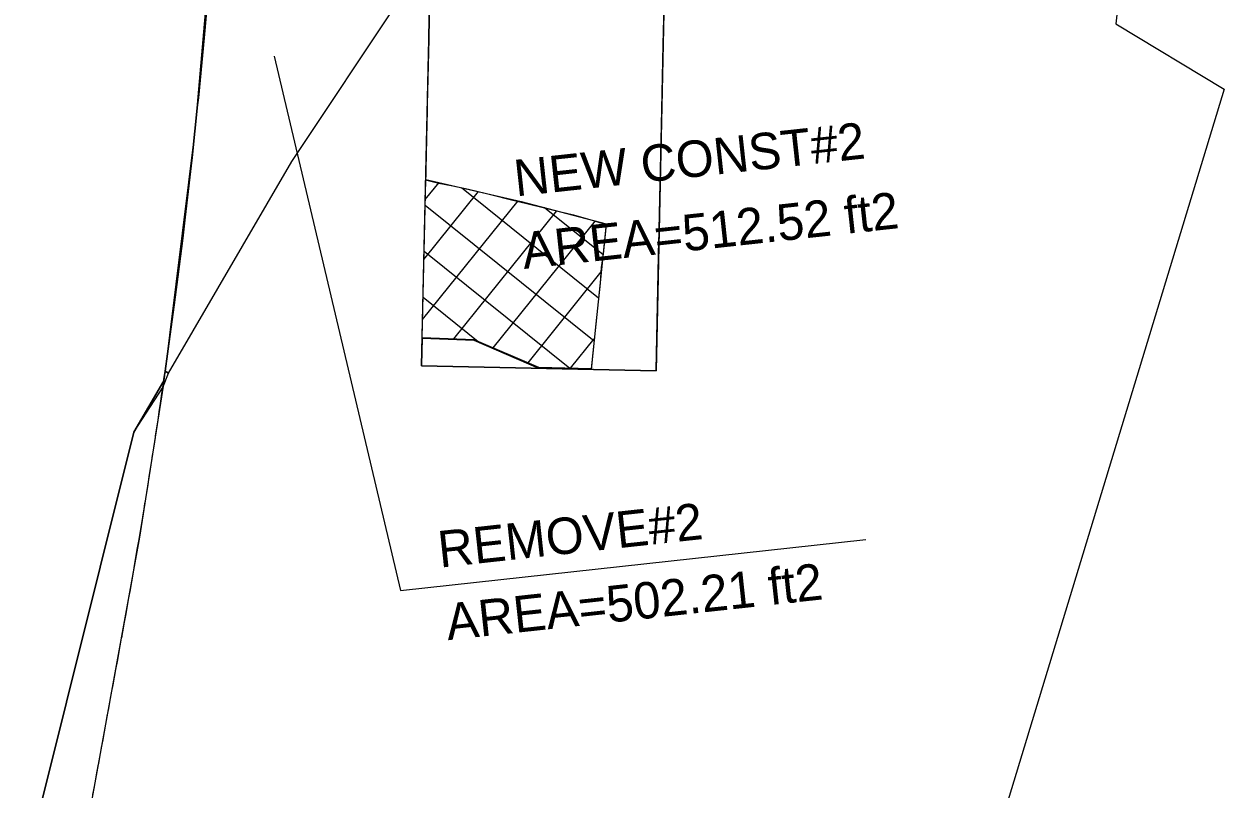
# Model space of a CAD drawing. Extents: x 1509538 to 1510847, y 401283 to 402022.
# Drawn here: x 1509791.8 to 1509883.9, y 401509.5 to 401568.2 of the extents above; entities that cross this region are included whole.
import ezdxf

# ---------------------------------------------------------------- set-up
doc = ezdxf.new("R2010")
doc.units = 0
for name, color, linetype in [('LAWE_P_T', 7, 'Continuous'), ('Level 10', 7, 'Continuous'), ('Level 2', 7, 'Continuous'), ('Level 24', 7, 'Continuous'), ('Level 3', 7, 'Continuous'), ('Level 4', 7, 'Continuous'), ('Level 7', 7, 'Continuous')]:
    doc.layers.add(name, color=color, linetype=linetype)

msp = doc.modelspace()

# ---------------------------------------------------------------- linework, layer by layer
at = {"layer": 'LAWE_P_T'}
msp.add_lwpolyline([(1509810.979, 401565.723), (1509820.68, 401524.728), (1509856.38, 401528.62)], dxfattribs=at)
at = {"layer": 'Level 10'}
for p, q in [((1509805.109, 401561.991), (1509805.163, 401562.527)), ((1509803.591, 401548.774), (1509803.964, 401551.755)), ((1509803.315, 401546.646), (1509803.591, 401548.774)), ((1509802.436, 401540.299), (1509802.86, 401541.4)), ((1509802.86, 401541.4), (1509802.614, 401541.544)), ((1509802.102, 401539.785), (1509802.436, 401540.299))]:
    msp.add_line(p, q, dxfattribs=at)
for points in [[(1509805.163, 401562.527), (1509805.605, 401567.117), (1509806.006, 401571.716), (1509806.049, 401572.248), (1509806.13, 401573.256), (1509806.21, 401574.264)], [(1509803.964, 401551.755), (1509804.156, 401553.354), (1509804.562, 401556.87), (1509804.68, 401557.938), (1509805.109, 401561.991)], [(1509802.614, 401541.544), (1509802.985, 401544.2), (1509803.315, 401546.646)], [(1509792.458, 401505.796), (1509800.217, 401536.878), (1509802.102, 401539.785)]]:
    msp.add_lwpolyline(points, dxfattribs=at)
at = {"layer": 'Level 2'}
for p, q in [((1509805.109, 401561.991), (1509805.163, 401562.527)), ((1509822.569, 401554.71), (1509823.627, 401556.027)), ((1509825.355, 401555.629), (1509835.868, 401547.182)), ((1509822.363, 401545.513), (1509829.687, 401554.629)), ((1509822.466, 401550.111), (1509826.657, 401555.328)), ((1509822.559, 401554.283), (1509835.521, 401543.87)), ((1509824.755, 401544.019), (1509832.657, 401553.855)), ((1509831.729, 401554.1), (1509836.216, 401550.495)), ((1509827.792, 401543.328), (1509835.621, 401553.074)), ((1509803.591, 401548.774), (1509803.964, 401551.755)), ((1509822.48, 401550.755), (1509833.67, 401541.765)), ((1509830.457, 401542.175), (1509836.077, 401549.17)), ((1509803.315, 401546.646), (1509803.591, 401548.774)), ((1509822.402, 401547.226), (1509826.626, 401543.832)), ((1509833.718, 401541.764), (1509835.537, 401544.028)), ((1509802.436, 401540.299), (1509802.86, 401541.4)), ((1509802.86, 401541.4), (1509802.614, 401541.544)), ((1509802.102, 401539.785), (1509802.436, 401540.299))]:
    msp.add_line(p, q, dxfattribs=at)
for points in [[(1509805.163, 401562.527), (1509805.605, 401567.117), (1509806.006, 401571.716), (1509806.049, 401572.248), (1509806.13, 401573.256), (1509806.21, 401574.264)], [(1509802.507, 401540.796), (1509802.525, 401540.921), (1509802.614, 401541.544), (1509802.985, 401544.2), (1509803.315, 401546.646), (1509803.591, 401548.774), (1509803.964, 401551.755), (1509804.156, 401553.354), (1509804.562, 401556.87), (1509804.68, 401557.938), (1509805.109, 401561.991), (1509805.163, 401562.527), (1509805.605, 401567.117), (1509805.605, 401567.119), (1509806.006, 401571.716)], [(1509803.964, 401551.755), (1509804.156, 401553.354), (1509804.562, 401556.87), (1509804.68, 401557.938), (1509805.109, 401561.991)], [(1509802.614, 401541.544), (1509802.985, 401544.2), (1509803.315, 401546.646)], [(1509772.308, 401394.175), (1509775.656, 401414.305), (1509783.793, 401462.538), (1509792.458, 401505.796), (1509800.217, 401536.878), (1509802.507, 401540.796)], [(1509792.458, 401505.796), (1509800.217, 401536.878), (1509802.102, 401539.785)]]:
    msp.add_lwpolyline(points, dxfattribs=at)
msp.add_lwpolyline([(1509822.603, 401556.263), (1509829.941, 401554.57), (1509836.463, 401552.852), (1509835.965, 401548.102), (1509835.296, 401541.728), (1509831.283, 401541.818), (1509826.334, 401543.959), (1509822.332, 401544.113)], close=True, dxfattribs=at)
at = {"layer": 'Level 24'}
msp.add_lwpolyline([(1509829.75, 401765.911), (1509866.097, 401667.732), (1509876.615, 401577.466), (1509875.566, 401568.188), (1509883.853, 401563.183), (1509866.769, 401506.877), (1509856.531, 401476.729), (1509809.074, 401412), (1509809.101, 401403.538), (1509796.557, 401386.395), (1509783.485, 401379.525), (1509778.168, 401371.598), (1509774.096, 401368.359), (1509767.585, 401349.346), (1509764.231, 401344.649), (1509737.941, 401349.46)], dxfattribs=at)
at = {"layer": 'Level 3'}
for p, q in [((1509822.948, 401571.989), (1509822.838, 401567.017)), ((1509822.28, 401541.962), (1509840.275, 401541.562))]:
    msp.add_line(p, q, dxfattribs=at)
for points in [[(1509840.275, 401541.562), (1509840.277, 401541.623), (1509840.388, 401546.621), (1509840.499, 401551.62), (1509840.502, 401551.752), (1509840.505, 401551.883), (1509840.508, 401552.015), (1509840.511, 401552.146), (1509840.514, 401552.278), (1509840.517, 401552.409), (1509840.52, 401552.541), (1509840.523, 401552.672), (1509840.526, 401552.804), (1509840.529, 401552.936), (1509840.532, 401553.067), (1509840.534, 401553.199), (1509840.537, 401553.33), (1509840.54, 401553.462), (1509840.543, 401553.593), (1509840.546, 401553.725), (1509840.549, 401553.856), (1509840.552, 401553.988), (1509840.555, 401554.119), (1509840.558, 401554.251), (1509840.561, 401554.383), (1509840.564, 401554.514), (1509840.567, 401554.646), (1509840.57, 401554.777), (1509840.573, 401554.909), (1509840.575, 401555.04), (1509840.578, 401555.172), (1509840.581, 401555.303), (1509840.584, 401555.435), (1509840.587, 401555.566), (1509840.59, 401555.698), (1509840.593, 401555.83), (1509840.596, 401555.961), (1509840.599, 401556.093), (1509840.602, 401556.224), (1509840.605, 401556.356), (1509840.608, 401556.487), (1509840.611, 401556.619), (1509840.614, 401556.75), (1509840.616, 401556.882), (1509840.619, 401557.013), (1509840.622, 401557.145), (1509840.625, 401557.277), (1509840.628, 401557.408), (1509840.631, 401557.54), (1509840.634, 401557.671), (1509840.637, 401557.803), (1509840.64, 401557.934), (1509840.643, 401558.066), (1509840.646, 401558.197), (1509840.649, 401558.329), (1509840.652, 401558.46), (1509840.655, 401558.592), (1509840.657, 401558.724), (1509840.66, 401558.855), (1509840.663, 401558.987), (1509840.666, 401559.118), (1509840.669, 401559.25), (1509840.672, 401559.381), (1509840.675, 401559.513), (1509840.678, 401559.644), (1509840.681, 401559.776), (1509840.684, 401559.908), (1509840.687, 401560.039), (1509840.69, 401560.171), (1509840.693, 401560.302), (1509840.696, 401560.434), (1509840.698, 401560.565), (1509840.701, 401560.697), (1509840.704, 401560.828), (1509840.707, 401560.96), (1509840.71, 401561.091), (1509840.713, 401561.223), (1509840.716, 401561.355), (1509840.719, 401561.486), (1509840.722, 401561.618), (1509840.833, 401566.616), (1509840.944, 401571.615)], [(1509822.838, 401567.017), (1509822.726, 401562.018), (1509822.723, 401561.887), (1509822.72, 401561.755), (1509822.718, 401561.624), (1509822.715, 401561.492), (1509822.712, 401561.36), (1509822.709, 401561.229), (1509822.706, 401561.097), (1509822.703, 401560.966), (1509822.7, 401560.834), (1509822.697, 401560.703), (1509822.694, 401560.571), (1509822.691, 401560.44), (1509822.688, 401560.308), (1509822.685, 401560.177), (1509822.682, 401560.045), (1509822.679, 401559.913), (1509822.677, 401559.782), (1509822.674, 401559.65), (1509822.671, 401559.519), (1509822.668, 401559.387), (1509822.665, 401559.256), (1509822.662, 401559.124), (1509822.659, 401558.993), (1509822.656, 401558.861), (1509822.653, 401558.73), (1509822.65, 401558.598), (1509822.647, 401558.466), (1509822.644, 401558.335), (1509822.641, 401558.203), (1509822.638, 401558.072), (1509822.636, 401557.94), (1509822.633, 401557.809), (1509822.63, 401557.677), (1509822.627, 401557.546), (1509822.624, 401557.414), (1509822.621, 401557.283), (1509822.618, 401557.151), (1509822.615, 401557.019), (1509822.612, 401556.888), (1509822.609, 401556.756), (1509822.606, 401556.625), (1509822.603, 401556.493), (1509822.6, 401556.362), (1509822.597, 401556.23), (1509823.624, 401555.984), (1509824.674, 401555.77), (1509825.882, 401555.508), (1509827.263, 401555.167), (1509827.879, 401555.027), (1509828.98, 401554.742), (1509830.46, 401554.39), (1509831.729, 401554.069), (1509832.526, 401553.872), (1509833.944, 401553.535), (1509835.205, 401553.191), (1509836.457, 401552.797), (1509836.3, 401551.298), (1509836.222, 401550.555), (1509836.181, 401550.167), (1509836.07, 401549.5), (1509835.979, 401548.31), (1509835.657, 401545.177), (1509835.29, 401541.673), (1509831.278, 401541.762), (1509826.328, 401543.903), (1509822.326, 401544.057), (1509822.281, 401542.023), (1509822.28, 401541.962)], [(1509802.507, 401540.796), (1509800.217, 401536.878), (1509792.458, 401505.796)], [(1509797.079, 401509.055), (1509797.189, 401509.656), (1509797.299, 401510.256), (1509797.409, 401510.857), (1509797.505, 401511.383), (1509797.519, 401511.458), (1509797.629, 401512.058), (1509797.739, 401512.659), (1509797.849, 401513.26), (1509797.959, 401513.861), (1509798.068, 401514.461), (1509798.178, 401515.062), (1509798.288, 401515.663), (1509798.398, 401516.263), (1509798.405, 401516.301), (1509798.508, 401516.864), (1509798.618, 401517.465), (1509798.728, 401518.066), (1509798.838, 401518.666), (1509798.948, 401519.267), (1509799.058, 401519.868), (1509799.168, 401520.468), (1509799.278, 401521.069), (1509799.305, 401521.219), (1509799.342, 401521.421), (1509799.389, 401521.677), (1509799.501, 401522.296), (1509799.613, 401522.915), (1509799.724, 401523.534), (1509799.835, 401524.154), (1509799.944, 401524.773), (1509800.053, 401525.392), (1509800.152, 401525.964), (1509800.161, 401526.012), (1509800.208, 401526.283), (1509800.268, 401526.632), (1509800.375, 401527.252), (1509800.48, 401527.872), (1509800.585, 401528.492), (1509800.689, 401529.112), (1509800.793, 401529.733), (1509800.896, 401530.353), (1509800.922, 401530.513), (1509800.998, 401530.974), (1509801.061, 401531.362), (1509801.099, 401531.595), (1509801.199, 401532.216), (1509801.299, 401532.837), (1509801.398, 401533.458), (1509801.496, 401534.079), (1509801.593, 401534.701), (1509801.651, 401535.069), (1509801.69, 401535.322), (1509801.786, 401535.944), (1509801.863, 401536.449), (1509801.881, 401536.566), (1509801.975, 401537.188), (1509802.069, 401537.81), (1509802.162, 401538.432), (1509802.254, 401539.054), (1509802.338, 401539.632), (1509802.345, 401539.676), (1509802.436, 401540.299), (1509802.507, 401540.796)]]:
    msp.add_lwpolyline(points, dxfattribs=at)
at = {"layer": 'Level 4'}
for p, q in [((1509812.343, 401557.623), (1509820.637, 401570.132)), ((1509802.86, 401541.4), (1509812.343, 401557.623))]:
    msp.add_line(p, q, dxfattribs=at)
for points in [[(1509806.006, 401571.716), (1509805.605, 401567.117), (1509805.163, 401562.527), (1509805.109, 401561.991), (1509804.68, 401557.938), (1509804.562, 401556.87), (1509804.156, 401553.354), (1509803.964, 401551.755), (1509803.591, 401548.774), (1509803.315, 401546.646), (1509802.985, 401544.2), (1509802.614, 401541.544)], [(1509802.614, 401541.544), (1509802.86, 401541.4)]]:
    msp.add_lwpolyline(points, dxfattribs=at)
at = {"layer": 'Level 7'}
for p, q in [((1509806.644, 401580.317), (1509804.895, 401559.964)), ((1509806.644, 401580.317), (1509804.895, 401559.964)), ((1509822.838, 401567.017), (1509823.056, 401578.281)), ((1509822.838, 401567.017), (1509823.056, 401578.281)), ((1509841.063, 401577.599), (1509840.275, 401541.562)), ((1509841.063, 401577.599), (1509840.275, 401541.562)), ((1509822.28, 401541.962), (1509822.838, 401567.017)), ((1509822.28, 401541.962), (1509822.838, 401567.017)), ((1509804.895, 401559.964), (1509802.458, 401540.386)), ((1509804.895, 401559.964), (1509802.458, 401540.386)), ((1509840.275, 401541.562), (1509822.28, 401541.962)), ((1509840.275, 401541.562), (1509822.28, 401541.962)), ((1509802.458, 401540.386), (1509800.637, 401528.802)), ((1509802.458, 401540.386), (1509800.637, 401528.802)), ((1509800.637, 401528.802), (1509792.242, 401482.624)), ((1509800.637, 401528.802), (1509792.242, 401482.624))]:
    msp.add_line(p, q, dxfattribs=at)

# ---------------------------------------------------------------- texts
at = {"layer": 'LAWE_P_T'}
for s, height, p in [('NEW CONST#2', 2.79999, (1509829.536, 401554.952)), ('AREA=512.52 ft2', 2.79999, (1509830.143, 401549.385)), ('REMOVE#2', 2.8, (1509823.702, 401526.466)), ('AREA=502.21 ft2', 2.79999, (1509824.309, 401520.899))]:
    msp.add_text(s, height=height, rotation=6.2219, dxfattribs=at).set_placement(p)

doc.saveas('drawing.dxf')
